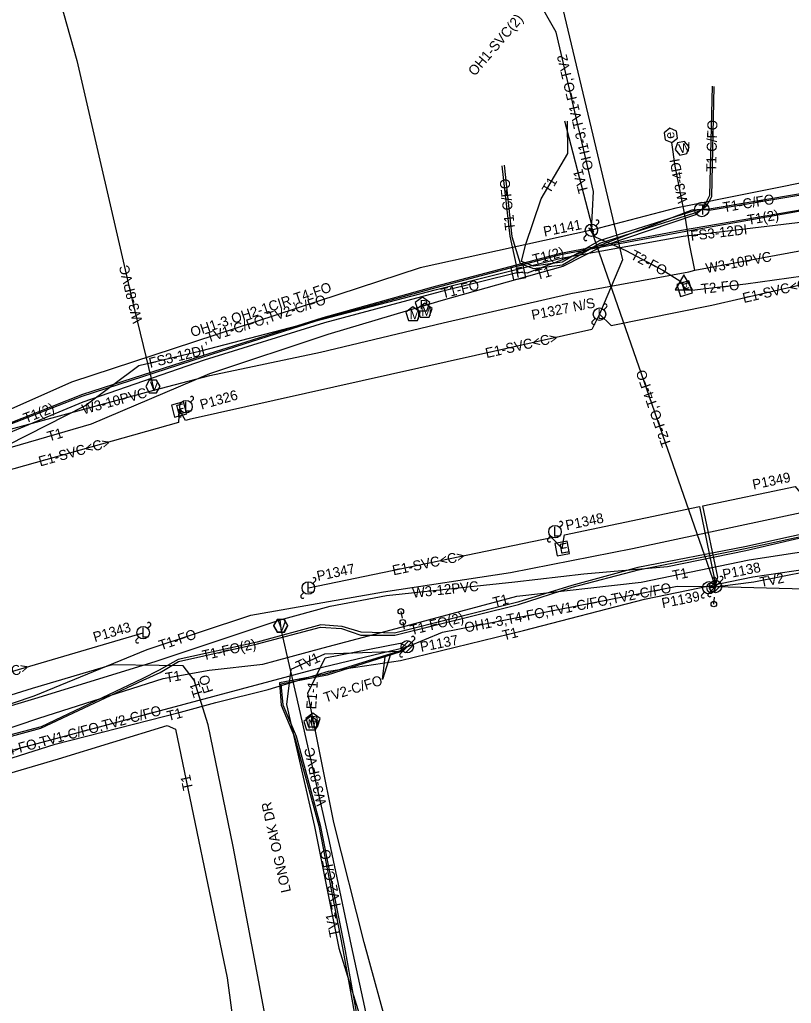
# Model space of a CAD drawing. Extents: x 2336688 to 2352634, y 362473 to 369571.
# Drawn here: x 2347179.1 to 2347488.6, y 367155.5 to 367550.3 of the extents above; entities that cross this region are included whole.
import ezdxf

# ---------------------------------------------------------------- set-up
doc = ezdxf.new("R2010")
doc.units = 0
for name, color, linetype in [('Default', 7, 'Continuous'), ('RD_EX_DV_Prop', 7, 'Continuous'), ('RD_EX_DV_TX_Prop', 7, 'Continuous'), ('RD_EX_RW', 7, 'Continuous'), ('RD_EX_RW_TX', 7, 'Continuous'), ('RD_HC_Data_Tic', 7, 'Continuous'), ('RD_PD_CstnLmt', 7, 'Continuous'), ('RD_PD_Final_TrvlWay', 7, 'Continuous'), ('RD_PD_PatLn3', 7, 'Continuous'), ('RD_PD_PatLn4', 7, 'Continuous'), ('RD_SHT_ShtClip', 7, 'Continuous'), ('RD_Sketch1', 7, 'Continuous'), ('RD_Sketch2', 7, 'Continuous'), ('RD_Sketch5', 7, 'Continuous'), ('RD_TX_Misc1', 7, 'Continuous')]:
    doc.layers.add(name, color=color, linetype=linetype)

# ---------------------------------------------------------------- blocks, each defined once
blk = doc.blocks.new('SUE_MUE')
at = {"layer": 'Default'}
blk.add_lwpolyline([(2.89, 0), (1.44, 2.5), (-1.44, 2.5), (-2.89, 0), (-1.44, -2.5), (1.44, -2.5)], close=True, dxfattribs=at)
blk.add_text('e', height=3.75, dxfattribs=at).set_placement((-1.32, -1.4))
blk = doc.blocks.new('GW')
at = {"layer": 'RD_HC_Data_Tic'}
blk.add_line((0, 0), (0, 5), dxfattribs=at)
blk.add_circle((0, 0), 2, dxfattribs=at)

msp = doc.modelspace()

# ---------------------------------------------------------------- linework, layer by layer
at = {"layer": 'RD_EX_RW'}
for p, q in [((2347327.82, 367295.69), (2347324.63, 367285.44)), ((2347324.63, 367285.44), (2347325.63, 367294.57))]:
    msp.add_line(p, q, dxfattribs=at)
at = {"layer": 'RD_EX_RW_TX'}
for points in [[(2347373.42, 367491.96), (2347376.57, 367463.32), (2347379.85, 367452.38), (2347385.16, 367450.4), (2347396.79, 367451.89), (2347411.84, 367460.6), (2347449.94, 367472.71), (2347452.74, 367474.1), (2347454.79, 367475.65), (2347456.79, 367479.39), (2347457.64, 367523.5)], [(2347456.94, 367523.58), (2347455.77, 367479.72), (2347454.26, 367476.51), (2347452.74, 367474.1)], [(2347452.74, 367474.1), (2347449.67, 367473.59), (2347411.53, 367461.54), (2347396.77, 367452.92), (2347385.24, 367451.42), (2347380.34, 367453.21), (2347381.99, 367459.76), (2347388.33, 367478.34), (2347399.04, 367496.52), (2347398.81, 367509.52)], [(2347408.44, 367465.79), (2347408.77, 367467.44), (2347397.78, 367509.52)], [(2347379.12, 367448.82), (2347378.45, 367451.78), (2347375.78, 367463.37), (2347372.58, 367491.64)], [(2347493.21, 367479.93), (2347455.71, 367473.66), (2347452.74, 367474.1), (2347448.74, 367473.85), (2347412.51, 367459.94), (2347396.43, 367453.77), (2347382.64, 367448.58), (2347379.12, 367448.82), (2347347.7, 367441.05), (2347301.35, 367428.58), (2347253.11, 367413.66), (2347204.34, 367396.75), (2347168.08, 367381.62), (2347139.54, 367369.91), (2347109.42, 367360.33), (2347060.14, 367343.81), (2347012.82, 367329.5), (2346964.23, 367313.72), (2346893.43, 367288.42), (2346890.71, 367286.97), (2346887.9, 367286.45), (2346775.81, 367246.88), (2346756.05, 367240.68)], [(2347493.07, 367480.59), (2347455.62, 367474.3), (2347452.74, 367474.1), (2347450.17, 367472.02), (2347413.02, 367459.45), (2347396.97, 367451.28), (2347348.05, 367437.46), (2347302.76, 367423.98), (2347255.28, 367408.11), (2347207.74, 367387.96), (2347168.62, 367376.63), (2347134.49, 367365.89), (2347110.11, 367358.5), (2347060.95, 367341.47), (2347013.68, 367326.75), (2346965.57, 367309.6), (2346919.17, 367294.2), (2346889.18, 367289.05), (2346836.21, 367315.04), (2346827.9, 367322.52), (2346822.65, 367340.13), (2346824.21, 367344.56)], [(2347493.75, 367473.66), (2347444.81, 367465.06), (2347396.07, 367455.9), (2347345.96, 367442.69), (2347300.78, 367430.21), (2347252.72, 367414.9), (2347203.98, 367399.02), (2347167.78, 367385.01), (2347137.95, 367372.86), (2347109.32, 367361.19), (2347059.71, 367345.57), (2347012.57, 367330.88), (2346963.45, 367316.33), (2346917.8, 367299.85), (2346891.73, 367292.36), (2346839.33, 367318.15), (2346829.05, 367325.03), (2346824.09, 367341.03), (2346824.21, 367344.56)], [(2347493.77, 367474.07), (2347444.64, 367465.68), (2347395.98, 367456.43), (2347345.81, 367443.17), (2347300.67, 367430.69), (2347252.46, 367415.35), (2347204.25, 367399.86), (2347167.66, 367385.47), (2347137.74, 367373.17), (2347109.3, 367361.85), (2347059.64, 367346.11), (2347012.51, 367331.46), (2346963.58, 367315.78), (2346917.62, 367300.41), (2346891.78, 367293.28), (2346839.99, 367318.61), (2346831.68, 367325.52), (2346825.4, 367341.75), (2346824.21, 367344.56)], [(2347408.44, 367465.79), (2347409.99, 367463.14), (2347422.24, 367457.62), (2347437.16, 367449.8), (2347443.92, 367445.45), (2347445.89, 367442.37), (2347448.67, 367441.77), (2347470.44, 367444.23), (2347499.15, 367448.23)], [(2346929.43, 366898.3), (2346926.24, 366950.27), (2346914.94, 366994.66), (2346903.95, 367048.72), (2346891.88, 367094.98), (2346882.43, 367148.75), (2346880.23, 367164.03), (2346885.05, 367187.76), (2346886.25, 367192.23), (2346889.58, 367192.85), (2346896.67, 367193.51), (2346947.77, 367206.59), (2346995.79, 367219.64), (2347046.69, 367235.53), (2347089.94, 367248.15), (2347136.19, 367262.43), (2347184.88, 367278.93), (2347230.19, 367297.47), (2347271.77, 367311.28), (2347325.01, 367320.63), (2347375.99, 367328.45), (2347424.9, 367338.06), (2347468.18, 367347.3), (2347525.21, 367359.4)], [(2347527.34, 367351.4), (2347470.01, 367338.79), (2347427.07, 367330.37), (2347400.52, 367323.15), (2347378.96, 367316.52), (2347329.42, 367304.08), (2347316.07, 367304.5), (2347308.43, 367306.77), (2347299.83, 367307.37), (2347274.3, 367300.44), (2347242.65, 367293.52), (2347235.04, 367289.17), (2347228.21, 367285.73), (2347187.63, 367266.43), (2347137.4, 367253.23)], [(2347455.53, 367322.31), (2347459.94, 367322.89), (2347473.65, 367324.69), (2347527.79, 367335.44), (2347581.01, 367348.1), (2347600.51, 367352.4), (2347603.18, 367342.01), (2347612.97, 367293.38)], [(2347137.76, 367252.45), (2347187.57, 367265.92), (2347228.62, 367285.2), (2347235.41, 367288.33), (2347242.77, 367292.66), (2347274.49, 367299.82), (2347299.77, 367306.49), (2347308.22, 367305.91), (2347315.97, 367303.25), (2347329.53, 367303.28), (2347379.14, 367315.65), (2347400.73, 367322.5), (2347427.35, 367329.48), (2347470.17, 367338.02), (2347527.74, 367350.46)], [(2346729.92, 367125.44), (2346760.09, 367132.46), (2346822.83, 367150.8), (2346847.92, 367159.43), (2346911.38, 367177.91), (2346957.67, 367191.14), (2346999.5, 367209.08), (2347049.12, 367224.56), (2347093.92, 367240.35), (2347120.7, 367252.77), (2347143.99, 367255.5), (2347186.71, 367269.91), (2347236.58, 367285.94), (2347255.06, 367289.24), (2347276.57, 367291.67), (2347281.58, 367292.99), (2347300.77, 367298.26), (2347328.04, 367305.43), (2347378.49, 367318.88), (2347428.36, 367324.58), (2347471.76, 367333.48), (2347528.47, 367342.27)], [(2346897.18, 367161.87), (2346897.33, 367167.15), (2346913.45, 367172.96), (2346960.85, 367184.91), (2347003.36, 367197.72), (2347054.81, 367213.14), (2347089.91, 367226.4), (2347147.29, 367244.91), (2347193.34, 367259.48), (2347243.62, 367272.38), (2347257.76, 367276.24), (2347278.69, 367281.44), (2347302.95, 367288.88), (2347331.85, 367293.13), (2347381.23, 367305.16), (2347429.75, 367317.72), (2347473.23, 367326.64), (2347527.97, 367334.66)], [(2347334.55, 367298.63), (2347331.8, 367296.93), (2347301.27, 367287.43), (2347283.36, 367284.15), (2347283.95, 367275.18), (2347289.35, 367262.51), (2347299.08, 367226.8), (2347308.57, 367177.85), (2347317.02, 367131.39), (2347310.94, 367129.7), (2347289.46, 367122.33), (2347280.81, 367117.06), (2347272.21, 367104.58), (2347262.49, 367096.82), (2347251.09, 367094.03)], [(2347334.55, 367298.63), (2347331.8, 367296.53), (2347302.45, 367287.2), (2347283.9, 367283.67), (2347284.61, 367275.35), (2347289.93, 367262.7), (2347299.68, 367227.09), (2347309.43, 367178.07), (2347317.83, 367131.2), (2347311.13, 367129.12), (2347289.71, 367122), (2347281.24, 367116.62), (2347272.75, 367104.22), (2347262.7, 367096.28), (2347251.22, 367093.33)], [(2347334.55, 367298.63), (2347331.8, 367296.73), (2347301.31, 367295.65), (2347287.81, 367289.55), (2347286.17, 367275.46), (2347297.32, 367226.43), (2347307.12, 367177.6), (2347322.94, 367126.73), (2347332.85, 367118.93), (2347345.67, 367117.58), (2347368.91, 367121.3)], [(2347251.53, 367092.27), (2347273.58, 367100.79), (2347279.31, 367110.51), (2347279.56, 367112.12), (2347281.17, 367113.65), (2347282.65, 367123.08), (2347274.25, 367168.45), (2347264.71, 367218.53), (2347254.72, 367267.34), (2347249.12, 367285.21), (2347244.59, 367290.99), (2347234.99, 367291.06), (2347216.14, 367291.34), (2347184.08, 367281.81), (2347138.56, 367267.72)], [(2347148.27, 367240), (2347194.65, 367253.63), (2347238.25, 367267.08), (2347241.57, 367265.57), (2347262.35, 367165.72), (2347268.45, 367119.85), (2347270.43, 367112.95), (2347273.7, 367113.96), (2347276.05, 367114.24), (2347274.41, 367113.29), (2347270.48, 367108.09), (2347263.45, 367101.7), (2347250.15, 367097.15)]]:
    msp.add_lwpolyline(points, dxfattribs=at)
for points in [[(2347381.06, 367451.77), (2347376.17, 367450.76), (2347377.18, 367445.87), (2347382.07, 367446.88)], [(2347447.55, 367445.49), (2347442.77, 367444.03), (2347444.22, 367439.25), (2347449.01, 367440.71)]]:
    msp.add_lwpolyline(points, close=True, dxfattribs=at)
msp.add_circle((2347452.74, 367474.1), 2.89, dxfattribs=at)
at = {"layer": 'RD_HC_Data_Tic'}
for p, q in [((2347410.2, 367467.55), (2347411.26, 367468.61)), ((2347405.61, 367462.96), (2347406.67, 367464.02)), ((2347413.43, 367433.88), (2347414.49, 367434.94)), ((2347408.83, 367429.28), (2347409.9, 367430.34)), ((2347247.56, 367396.74), (2347248.62, 367397.8)), ((2347242.96, 367392.15), (2347244.02, 367393.21)), ((2347395.63, 367346.56), (2347396.69, 367347.62)), ((2347391.03, 367341.96), (2347392.09, 367343.03)), ((2347296.66, 367323.99), (2347297.72, 367325.05)), ((2347455.79, 367322.14), (2347458.85, 367325.2)), ((2347456.44, 367321.02), (2347459.97, 367324.55)), ((2347457.3, 367324.08), (2347458.36, 367325.14)), ((2347459.97, 367324.55), (2347461.03, 367325.61)), ((2347292.06, 367319.39), (2347293.13, 367320.45)), ((2347452.71, 367319.48), (2347453.77, 367320.55)), ((2347455.38, 367319.96), (2347456.44, 367321.02)), ((2347457.56, 367320.37), (2347460.62, 367323.43)), ((2347230.39, 367306.03), (2347231.45, 367307.09)), ((2347225.8, 367301.44), (2347226.86, 367302.5)), ((2347332.13, 367297.98), (2347335.19, 367301.05)), ((2347332.78, 367296.86), (2347336.31, 367300.4)), ((2347336.31, 367300.4), (2347337.38, 367301.46)), ((2347331.72, 367295.8), (2347332.78, 367296.86)), ((2347333.9, 367296.22), (2347336.96, 367299.28))]:
    msp.add_line(p, q, dxfattribs=at)
msp.add_lwpolyline([(2347408.04, 367467.79), (2347408.87, 367465.78), (2347407.41, 367466.58), (2347409.29, 367463.9), (2347409.29, 367463.9), (2347408.09, 367466), (2347409.47, 367465.19)], close=True, dxfattribs=at)
for centre in [(2347408.44, 367465.79), (2347411.66, 367432.11), (2347245.79, 367394.98), (2347393.86, 367344.79), (2347294.89, 367322.22), (2347455.53, 367322.31), (2347458.2, 367322.79), (2347228.62, 367304.26), (2347334.55, 367298.63)]:
    msp.add_circle(centre, 2.5, dxfattribs=at)
for centre, start, end in [((2347410.73, 367469.14), 315, 135), ((2347406.14, 367462.43), 135, 315), ((2347413.96, 367435.47), 315, 135), ((2347409.37, 367428.75), 135, 315), ((2347248.09, 367398.33), 315, 135), ((2347243.49, 367391.62), 135, 315), ((2347396.16, 367348.15), 315, 135), ((2347391.56, 367341.43), 135, 315), ((2347297.19, 367325.58), 315, 135), ((2347457.83, 367325.67), 315, 135), ((2347460.5, 367326.14), 315, 135), ((2347455.91, 367319.43), 135, 315), ((2347292.59, 367318.86), 135, 315), ((2347453.24, 367318.95), 135, 315), ((2347230.92, 367307.62), 315, 135), ((2347226.33, 367300.91), 135, 315), ((2347336.85, 367301.99), 315, 135), ((2347332.25, 367295.27), 135, 315)]:
    msp.add_arc(centre, 0.75, start, end, dxfattribs=at)
at = {"layer": 'RD_PD_Final_TrvlWay'}
for points in [[(2347365.04, 367648.59), (2347375.04, 367646.81), (2347420.85, 367453.86), (2347411.66, 367432.11), (2347408.65, 367425.96), (2347247.09, 367389.8), (2347245.57, 367389.37), (2347243.03, 367393.87), (2347242.83, 367388.6), (2347145.71, 367361.39), (2347142.58, 367366.06), (2347142.34, 367360.37), (2347024.46, 367322.51), (2347021.03, 367327.02), (2347021.01, 367321.39), (2346880.04, 367274.9), (2346876.34, 367279.3), (2346876.12, 367273.62), (2346794.47, 367247.23), (2346765.54, 367237.88), (2346760.44, 367241.84)], [(2347411.66, 367432.11), (2347416.41, 367427.52), (2347456.82, 367435.65), (2347514.93, 367449.13), (2347514.86, 367455.85), (2347518.86, 367450.04), (2347527.31, 367452), (2347598.1, 367470.08), (2347638.25, 367479.98), (2347637.21, 367489.58), (2347641.7, 367480.84), (2347702.59, 367495.22), (2347742.38, 367503.56), (2347770.63, 367508.97), (2347781.57, 367511.28), (2347780.95, 367520.78), (2347786.97, 367511.95), (2347822.4, 367519.43), (2347860.67, 367526.84), (2347915.43, 367542.21), (2347917.26, 367549.2)], [(2347294.89, 367322.22), (2347392.4, 367342.51), (2347396.75, 367338.07), (2347397.64, 367343.6), (2347451.77, 367354.89), (2347457.75, 367326.25), (2347458.2, 367322.79), (2347459.12, 367326.53), (2347453.14, 367355.18), (2347490.16, 367362.9), (2347494.09, 367358.25), (2347495.64, 367364.04), (2347579.56, 367381.55)], [(2346900.17, 367199.42), (2347008.96, 367235.37), (2347049.36, 367249.06), (2347056.78, 367227.15), (2347058.34, 367224.76), (2347058.11, 367227.6), (2347050.69, 367249.51), (2347105.72, 367268.16), (2347228.62, 367304.26)], [(2347367.97, 367126.47), (2347344.52, 367126.44), (2347334.62, 367131.11), (2347327.84, 367141.36), (2347317.23, 367179.92), (2347305.06, 367228.1), (2347294.65, 367280.06), (2347301.58, 367294.16), (2347331.76, 367300.13), (2347334.55, 367298.63)]]:
    msp.add_lwpolyline(points, dxfattribs=at)
for points in [[(2347244.82, 367396.92), (2347239.98, 367395.65), (2347241.24, 367390.82), (2347246.08, 367392.08)], [(2347398.75, 367340.99), (2347393.83, 367340.07), (2347394.76, 367335.15), (2347399.67, 367336.07)]]:
    msp.add_lwpolyline(points, close=True, dxfattribs=at)
at = {"layer": 'RD_PD_PatLn3'}
msp.add_lwpolyline([(2347445.49, 367447.93), (2347442.03, 367441.93), (2347448.96, 367441.93)], close=True, dxfattribs=at)
at = {"layer": 'RD_SHT_ShtClip'}
msp.add_line((2347458.2, 367322.79), (2347408.44, 367465.79), dxfattribs=at)
for points in [[(2347408.44, 367465.79), (2347409.31, 367481.28), (2347394.36, 367545.31), (2347386.71, 367558.81)], [(2347721.24, 367528.57), (2347686.62, 367523.73), (2347442.35, 367474.67), (2347408.44, 367465.79)], [(2347408.44, 367465.79), (2347339.72, 367450.68), (2347199.91, 367404.81), (2347135.6, 367376.27)], [(2347458.2, 367322.79), (2347494.08, 367321.83), (2347651.8, 367353.28), (2347684.57, 367367.93)], [(2347334.55, 367298.63), (2347348.68, 367304.54), (2347442.89, 367322.94), (2347458.2, 367322.79)], [(2347058.34, 367224.76), (2347091.91, 367234.67), (2347300.5, 367290.46), (2347334.55, 367298.63)]]:
    msp.add_lwpolyline(points, dxfattribs=at)
at = {"layer": 'RD_Sketch2'}
for points in [[(2347106.7, 367872.75), (2347119.56, 367828.07), (2347143.96, 367735.91), (2347160.5, 367679.49), (2347187.45, 367585.86), (2347201.96, 367533.94), (2347224.24, 367437.74), (2347231.88, 367406.34), (2347232.91, 367401.6)], [(2347449.95, 367449.7), (2347447.77, 367460.33), (2347446.18, 367470.62), (2347442.1, 367491.56), (2347440.76, 367500.98)], [(2347134.18, 367373.81), (2347167.37, 367383.79), (2347232.91, 367401.6), (2347255.39, 367407.5), (2347299.78, 367416.9), (2347348.96, 367428.56), (2347400.21, 367440.41), (2347447.52, 367449.07), (2347449.95, 367449.7), (2347496.38, 367458.28)], [(2346907.18, 367191.36), (2346908.2, 367188.48), (2346918.67, 367191.57), (2346952.96, 367203.21), (2346996.26, 367217.42), (2347046.54, 367233.83), (2347089.24, 367248.48), (2347137.8, 367263.72), (2347185.19, 367277.87), (2347233.41, 367292.66), (2347283.51, 367309.44), (2347303.65, 367314.93), (2347326.25, 367319.14), (2347377.74, 367324.63), (2347405.39, 367327.95), (2347438.97, 367330.87), (2347470.35, 367337.23), (2347531.2, 367351.47)], [(2347334.3, 367072.61), (2347332.51, 367081.63), (2347328.41, 367103.77), (2347322.65, 367130.6), (2347312.24, 367178.63), (2347303.42, 367220.52), (2347290.42, 367277.78), (2347284.28, 367304.45), (2347284.15, 367304.81), (2347283.51, 367309.44)]]:
    msp.add_lwpolyline(points, dxfattribs=at)
for points in [[(2347447.72, 367499.27), (2347445.82, 367501.44), (2347442.98, 367500.88), (2347442.06, 367498.14), (2347443.96, 367495.97), (2347446.79, 367496.53)], [(2347340.68, 367438.93), (2347337.78, 367436.83), (2347338.88, 367433.42), (2347342.47, 367433.42), (2347343.58, 367436.83)], [(2347336.85, 367435.02), (2347333.95, 367432.92), (2347335.06, 367429.51), (2347338.64, 367429.51), (2347339.75, 367432.92)], [(2347341.59, 367436.47), (2347338.69, 367434.36), (2347339.79, 367430.95), (2347343.38, 367430.95), (2347344.49, 367434.36)], [(2347235.39, 367403.09), (2347233.95, 367405.59), (2347231.06, 367405.59), (2347229.62, 367403.09), (2347231.06, 367400.59), (2347233.95, 367400.59)], [(2347286.66, 367307.1), (2347285.22, 367309.6), (2347282.33, 367309.6), (2347280.89, 367307.1), (2347282.33, 367304.6), (2347285.22, 367304.6)], [(2347286.71, 367307.03), (2347285.27, 367309.53), (2347282.38, 367309.53), (2347280.94, 367307.03), (2347282.38, 367304.53), (2347285.27, 367304.53)], [(2347295.98, 367270.76), (2347293.08, 367268.66), (2347294.19, 367265.25), (2347297.77, 367265.25), (2347298.88, 367268.66)], [(2347296.73, 367271.96), (2347293.83, 367269.86), (2347294.94, 367266.45), (2347298.52, 367266.45), (2347299.63, 367269.86)]]:
    msp.add_lwpolyline(points, close=True, dxfattribs=at)
at = {"layer": 'RD_Sketch5'}
msp.add_lwpolyline([(2346889.8, 367282.74), (2346919.7, 367292.87), (2346965.73, 367307.3), (2347014.03, 367323.63), (2347062.01, 367339.53), (2347111.01, 367356.83), (2347134.82, 367365.07), (2347159.13, 367371.92), (2347205.14, 367395.36), (2347226.9, 367411.47), (2347251.72, 367417.37), (2347346.28, 367442.06), (2347396.34, 367454.61), (2347445.27, 367463.42), (2347494.44, 367469.25)], dxfattribs=at)

# ---------------------------------------------------------------- block references
at = {"layer": 'RD_HC_Data_Tic'}
for p, xscale, yscale, rotation in [((2347457.57, 367315.75), 0.5546771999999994, 0.5546771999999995, -5.782765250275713), ((2347331.97, 367312.81), 0.5546771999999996, 0.5546771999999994, -169.27626398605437), ((2347332.76, 367308.46), 0.5546771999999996, 0.5546771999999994, -169.27626398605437)]:
    msp.add_blockref('GW', p, dxfattribs=dict(at, xscale=xscale, yscale=yscale, rotation=rotation))
at = {"layer": 'RD_Sketch2', "rotation": 98.10284866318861}
msp.add_blockref('SUE_MUE', (2347440.35, 367503.83), dxfattribs=at)

# ---------------------------------------------------------------- texts
at = {"layer": 'RD_EX_DV_Prop'}
for s, rotation, p in [('E1-SVC<C>', 13.0568, (2347469.6, 367436.56)), ('E1-SVC<C>', 12.6181, (2347366.38, 367414.45)), ('E1-SVC<C>', 15.652, (2347187.29, 367370.96)), ('E1-SVC<C>', 11.7539, (2347329.03, 367327.28)), ('E1-SVC<C>', 16.3721, (2347154.75, 367280.48)), ('E1-1', 86.5031, (2347298, 367273.44))]:
    msp.add_text(s, height=4, rotation=rotation, dxfattribs=at).set_placement(p)
at = {"layer": 'RD_EX_DV_TX_Prop'}
for s, rotation, p in [('P1141', 11.3573, (2347389.6, 367463.23)), ('P1327 N/S', 11.3573, (2347384.82, 367429.75)), ('P1326', 15.652, (2347252.03, 367393.77)), ('P1349', 11.7539, (2347473.49, 367361.7)), ('P1348', 11.7539, (2347398.51, 367345.36)), ('P1347', 11.7539, (2347298.7, 367325)), ('P1138', 11.2785, (2347461.47, 367325.69)), ('P1139', 11.0525, (2347437.03, 367314.13)), ('P1343', 16.3203, (2347209.2, 367300.47)), ('P1137', 11.0525, (2347340.14, 367296.56))]:
    msp.add_text(s, height=4, rotation=rotation, dxfattribs=at).set_placement(p)
at = {"layer": 'RD_EX_RW'}
for s, rotation, p in [('T1-C/FO', 88.4772, (2347458.47, 367489.21)), ('TV1', 104.6401, (2347407.26, 367481.15)), ('T1-C/FO', 96.2837, (2347377.83, 367465.99)), ('T1', 59.494, (2347391.74, 367480.19)), ('T1-C/FO', 9.4935, (2347461.54, 367472.99)), ('T1(2)', 9.9592, (2347471.34, 367467.91)), ('T1(2)', 14.7678, (2347385.43, 367452.06)), ('T2-FO', 332.3655, (2347423.8, 367454.54)), ('T1', 15.7757, (2347386.74, 367445.77)), ('T1-FO', 13.8941, (2347348.77, 367438.37)), ('T2-FO', 6.4517, (2347452.63, 367440.21)), ('T1(2)', 21.1541, (2347181.47, 367388.3)), ('T1', 16.1562, (2347190.79, 367380.97)), ('T1', 11.5866, (2347441.36, 367325.21)), ('TV2', 11.2277, (2347476.44, 367322.51)), ('T1', 14.9351, (2347369.49, 367314.42)), ('T1-FO(2)', 13.9974, (2347336.23, 367303.27)), ('T1-FO', 18.3746, (2347235.66, 367297.18)), ('T1', 13.6986, (2347373.28, 367301.16)), ('T1-FO(2)', 12.7142, (2347252.78, 367293.13)), ('TV1', 24.3105, (2347290.98, 367288.79)), ('T1', 10.1356, (2347237.94, 367284.15)), ('T1-', 107.7601, (2347252.74, 367279.08)), ('FO', 107.7601, (2347256.84, 367280.72)), ('TV2-C/FO', 17.2856, (2347301.72, 367276.22)), ('T1', 14.3834, (2347238.67, 367268.78)), ('T1', 101.7562, (2347248.63, 367241.46)), ('TV2-C/FO', 101.3467, (2347308.18, 367193.78)), ('TV1', 101.3467, (2347307.5, 367182.57))]:
    msp.add_text(s, height=4, rotation=rotation, dxfattribs=at).set_placement(p)
at = {"layer": 'RD_EX_RW_TX'}
msp.add_text('T', height=4.12, dxfattribs=at).set_placement((2347451.41, 367472.03))
for rotation, p in [(11.6664, (2347378.41, 367446.63)), (16.9682, (2347445.39, 367440.13))]:
    msp.add_text('F', height=4, rotation=rotation, dxfattribs=at).set_placement(p)
at = {"layer": 'RD_HC_Data_Tic'}
for p in [(2347410.85, 367430.17), (2347244.98, 367393.04), (2347393.05, 367342.86), (2347294.08, 367320.29), (2347227.81, 367302.33)]:
    msp.add_text('L', height=4, rotation=360, dxfattribs=at).set_placement(p)
msp.add_text('O', height=4, dxfattribs=at).set_placement((2347454.24, 367320.31))
at = {"layer": 'RD_PD_CstnLmt'}
for s, rotation, p in [('W3-4DI', 101.0224, (2347447.11, 367477.04)), ('W3-10PVC', 10.4723, (2347454.67, 367448.54)), ('W3-8PVC', 103.7691, (2347228.38, 367429.04)), ('W3-10PVC', 15.2036, (2347204.66, 367391.85)), ('W3-12PVC', 6.0913, (2347336.81, 367318.25)), ('W3-8PVC', 102.4406, (2347302.15, 367235.29))]:
    msp.add_text(s, height=4, rotation=rotation, dxfattribs=at).set_placement(p)
at = {"layer": 'RD_PD_Final_TrvlWay'}
for rotation, p in [(14.6296, (2347242.36, 367391.62)), (10.6261, (2347395.93, 367335.88))]:
    msp.add_text('E', height=4, rotation=rotation, dxfattribs=at).set_placement(p)
at = {"layer": 'RD_PD_PatLn3'}
msp.add_text('U', height=2.4, dxfattribs=at).set_placement((2347444.74, 367442.73))
at = {"layer": 'RD_PD_PatLn4'}
for s, rotation, p in [('OH1-SVC(2)', 49.4608, (2347361.64, 367527.39)), ('OH1-3,TV1-FO,TV2', 103.1458, (2347409.25, 367490.35)), ('OH1-3,OH2-1CIR,T4-FO', 18.1651, (2347248.31, 367422.84)), (',TV1-C/FO,TV2-C/FO', 18.1651, (2347253.18, 367420.18)), ('T2-FO,T4-FO', 109.1895, (2347440.58, 367379.62)), ('OH1-3,T4-FO,TV1-C/FO,TV2-C/FO', 11.0525, (2347357.92, 367304.3)), ('OH1-3,T4-FO,TV1-C/FO,TV2-C/FO', 14.9737, (2347154.68, 367249.52))]:
    msp.add_text(s, height=4, rotation=rotation, dxfattribs=at).set_placement(p)
at = {"layer": 'RD_Sketch1'}
for rotation, p in [(6.7575, (2347448.44, 367461.54)), (13.3723, (2347231.43, 367410.53))]:
    msp.add_text('FS3-12DI', height=4, rotation=rotation, dxfattribs=at).set_placement(p)
at = {"layer": 'RD_Sketch2'}
for s, rotation, p in [('W', 11.2332, (2347443.89, 367496.6)), ('P', 360, (2347339.53, 367434.01)), ('P', 360, (2347295.58, 367267.04))]:
    msp.add_text(s, height=3.75, rotation=rotation, dxfattribs=at).set_placement(p)
for s, p in [('M', (2347340.22, 367431.43)), ('M', (2347335.48, 367429.98)), ('V', (2347231.3, 367401.22)), ('V', (2347282.57, 367305.22)), ('V', (2347282.62, 367305.15)), ('M', (2347294.61, 367265.72))]:
    msp.add_text(s, height=3.75, dxfattribs=at).set_placement(p)
at = {"layer": 'RD_TX_Misc1'}
msp.add_text('LONG OAK DR', height=4, rotation=102.5715, dxfattribs=at).set_placement((2347287.95, 367200.44))

doc.saveas('drawing.dxf')
